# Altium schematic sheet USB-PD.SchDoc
size A2; SheetNumber: 2; SheetTotal: 17
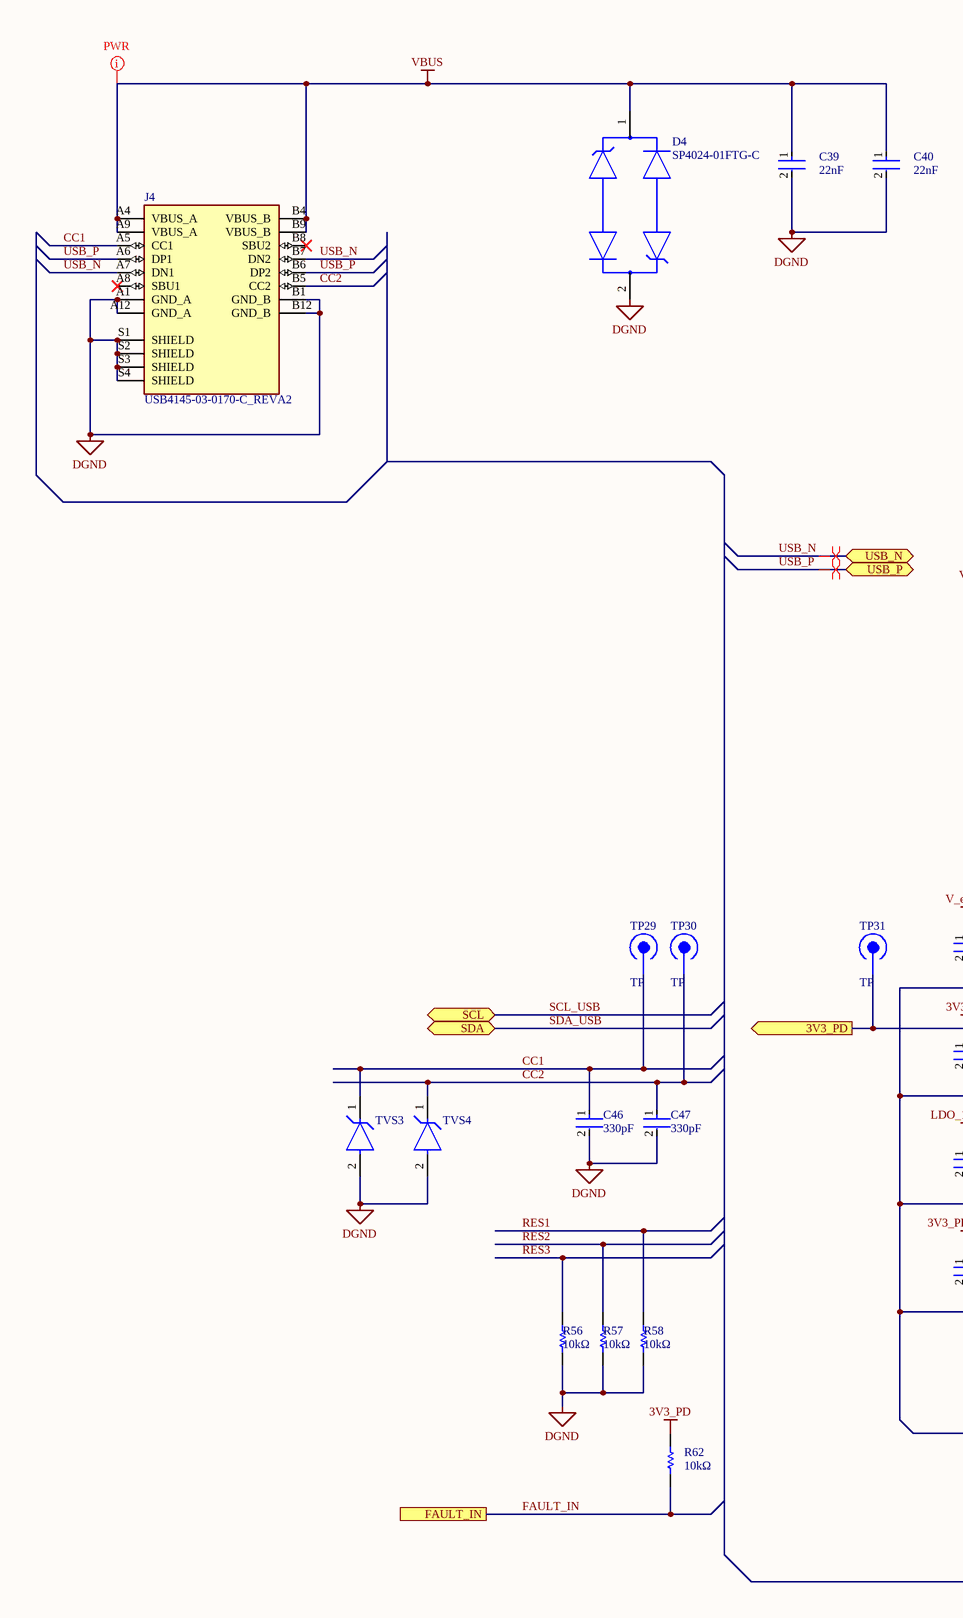
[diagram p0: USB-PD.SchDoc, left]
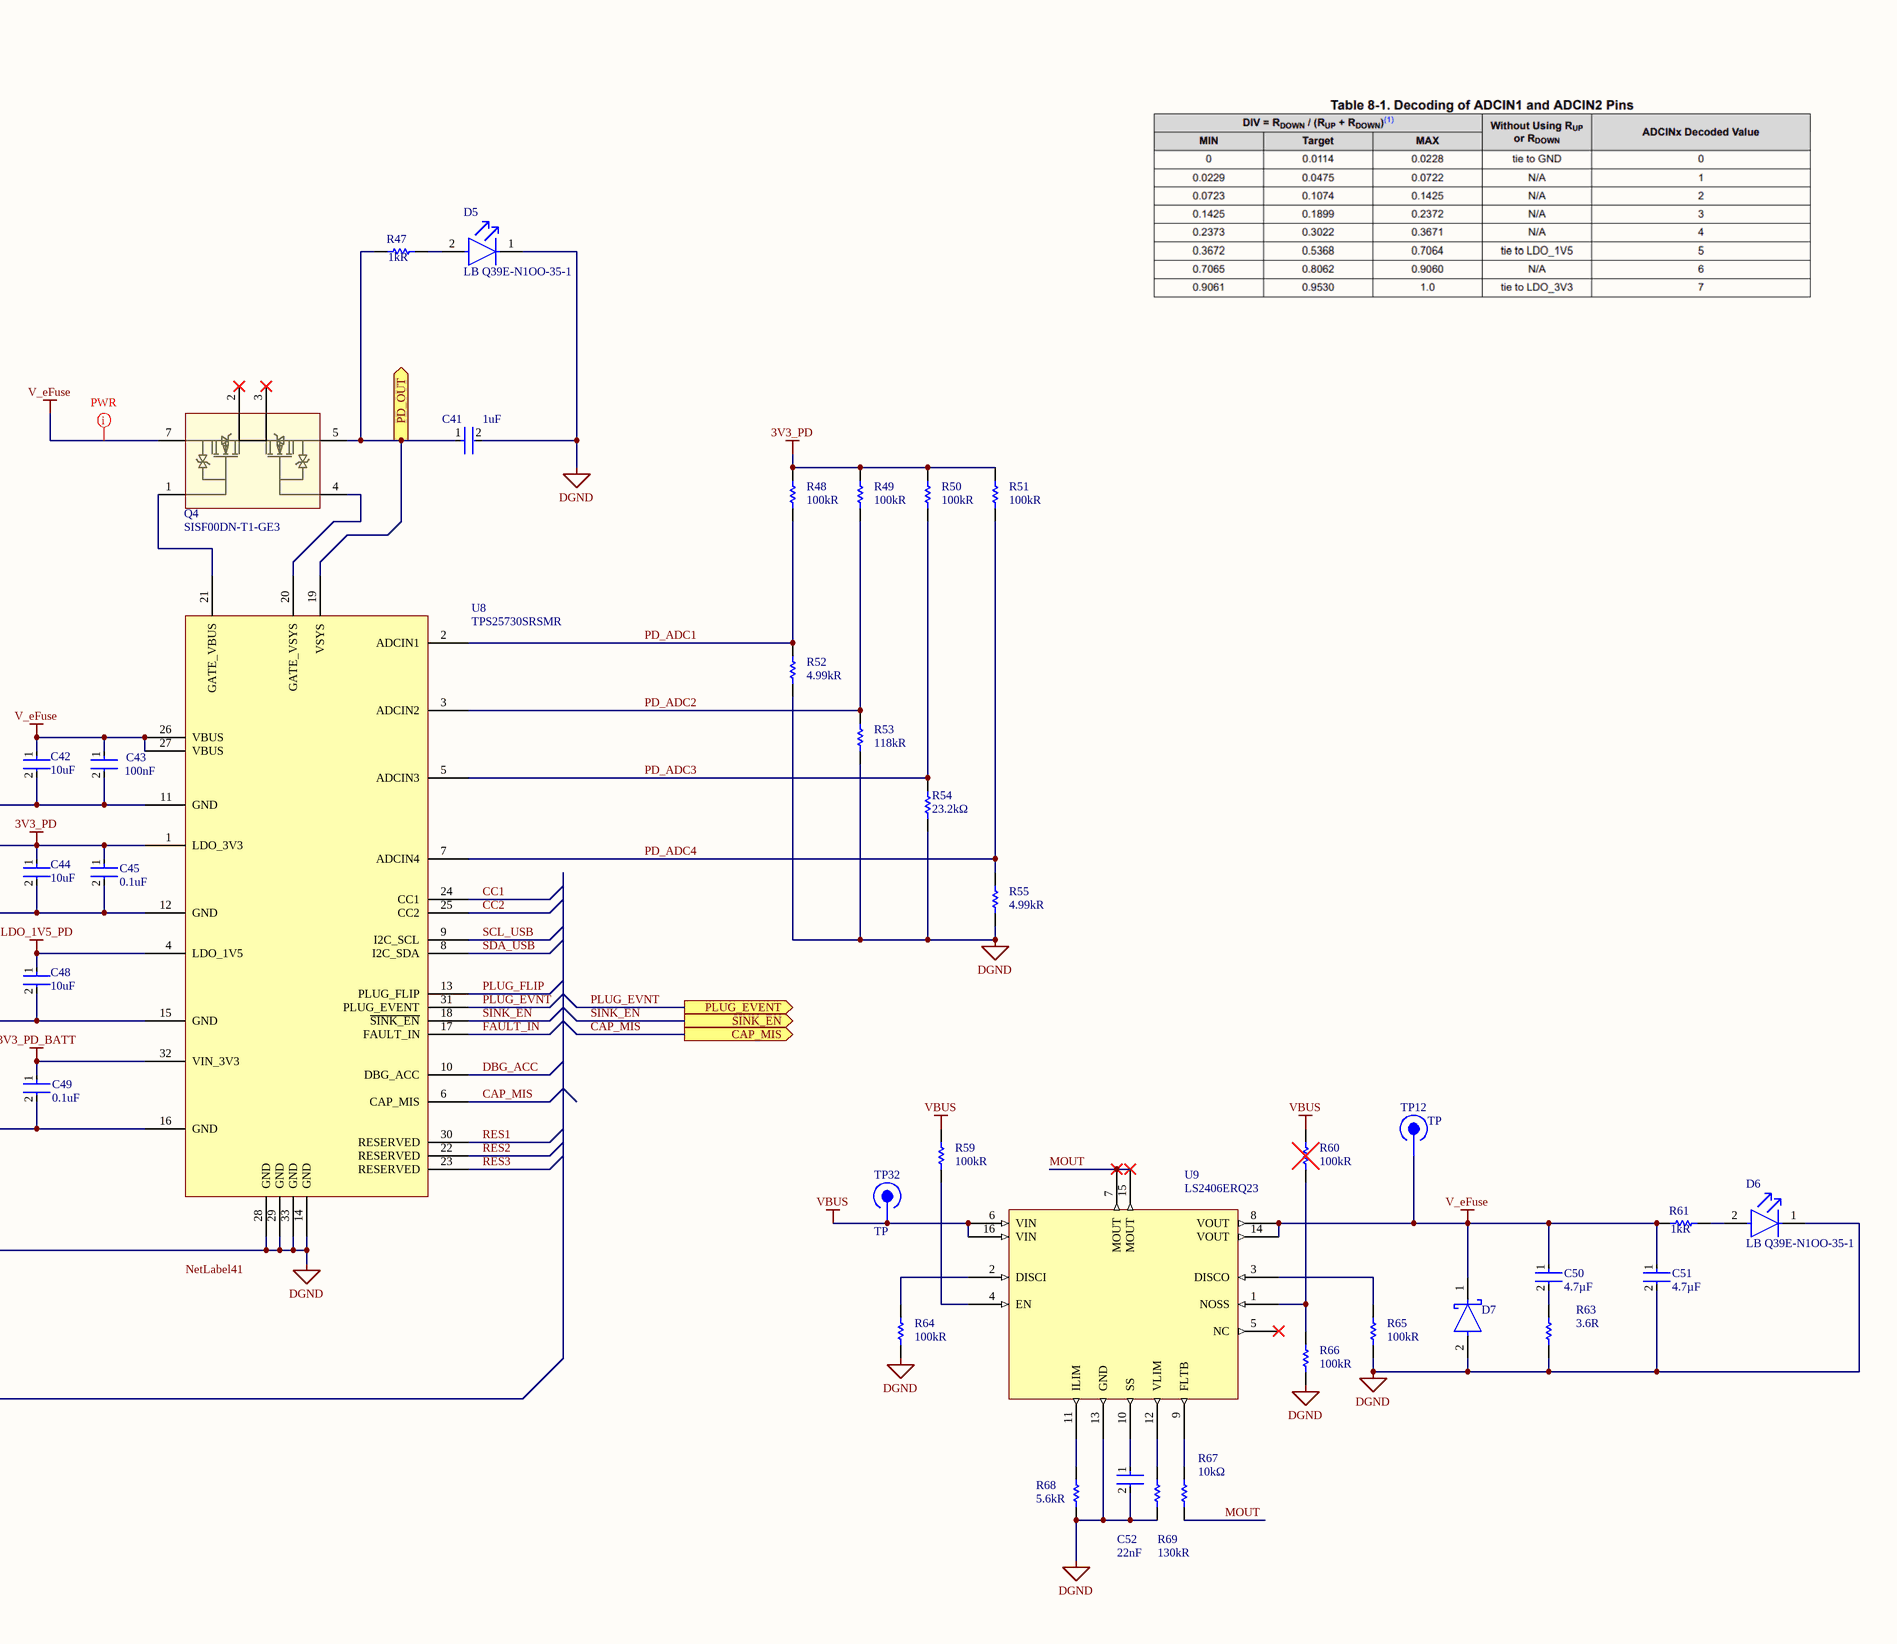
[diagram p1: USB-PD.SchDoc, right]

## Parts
C39  value 22nF  [FP-GRM155-0_05-MFG]  (hidden comment: GRM155R71H223KA12D)
C40  value 22nF  [FP-GRM155-0_05-MFG]  (hidden comment: GRM155R71H223KA12D)
C41  value 1uF  [FP-GCM188-0_1-IPC_B]  (hidden comment: GCM188R71E105KA64J)
C42  value 10uF  [FP-GRM155-0_2-MFG]  (hidden comment: GRM155R61A106ME11D)
C43  value 100nF  [FP-CC0402-IPC_B]  (hidden comment: CC0402KRX7R9BB104)
C44  value 10uF  [FP-GRM155-0_2-MFG]  (hidden comment: GRM155R61A106ME11D)
C45  value 0.1uF  [FP-CC0402-IPC_C]  (hidden comment: CC0402KRX7R7BB104)
C46  value 330pF  [FP-C0402-BB-MFG]  (hidden comment: C0402C331K5RACTU)
C47  value 330pF  [FP-C0402-BB-MFG]  (hidden comment: C0402C331K5RACTU)
C48  value 10uF  [FP-GRM155-0_2-MFG]  (hidden comment: GRM155R61A106ME11D)
C49  value 0.1uF  [FP-CC0402-IPC_C]  (hidden comment: CC0402KRX7R7BB104)
C50  value 4.7µF  [FP-GRM21B-0_15-IPC_A]  (hidden comment: GRM21BR61H475KE51L)
C51  value 4.7µF  [FP-GRM21B-0_15-IPC_A]  (hidden comment: GRM21BR61H475KE51L)
C52  value 22nF  [FP-GRM155-0_05-MFG]  (hidden comment: GRM155R71H223KA12D)
D4  SP4024-01FTG-C  [FP-SP4024-CA-MFG]
D5  LB Q39E-N1OO-35-1  [FP-LB_Q39E-MFG]
D6  LB Q39E-N1OO-35-1  [FP-LB_Q39E-MFG]
D7  PMEG4030ER,115  [FP-SOD123W-MFG]  (value not drawn)
J4  USB4145-03-0170-C_REVA2  [GCT_USB4145-03-0170-C_REVA2]
Q4  SISF00DN-T1-GE3  [New footprint 1]
R47  value 1kR  [FP-ERA2A-MFG]  (hidden comment: ERA-2AEB102X)
R48  value 100kR  [RESC1005X40X25LL10T10]  (hidden comment: RK73H1ETTP1003F)
R49  value 100kR  [RESC1005X40X25LL10T10]  (hidden comment: RK73H1ETTP1003F)
R50  value 100kR  [RESC1005X40X25LL10T10]  (hidden comment: RK73H1ETTP1003F)
R51  value 100kR  [RESC1005X40X25LL10T10]  (hidden comment: RK73H1ETTP1003F)
R52  value 4.99kR  [RESC1005X40X25LL10T10]  (hidden comment: RK73H1ETTP4991F)
R53  value 118kR  [RESC1005X40X25LL10T10]  (hidden comment: RK73H1ETTP1183F)
R54  value 23.2kΩ  [RESC1005X40X25LL10T10]  (hidden comment: RK73H1ETTP2322F)
R55  value 4.99kR  [RESC1005X40X25LL10T10]  (hidden comment: RK73H1ETTP4991F)
R56  value 10kΩ  [RESC1005X40X25LL10T10]  (hidden comment: RK73B1ETTP103J)
R57  value 10kΩ  [RESC1005X40X25LL10T10]  (hidden comment: RK73B1ETTP103J)
R58  value 10kΩ  [RESC1005X40X25LL10T10]  (hidden comment: RK73B1ETTP103J)
R59  value 100kR  [RESC1005X40X25LL10T10]  (hidden comment: RK73H1ETTP1003F)
R60  value 100kR  [RESC1005X40X25LL10T10]  (hidden comment: RK73H1ETTP1003F)  (no BOM)
R61  value 1kR  [FP-ERA2A-MFG]  (hidden comment: ERA-2AEB102X)
R62  value 10kΩ  [RESC1005X40X25LL10T10]  (hidden comment: RK73B1ETTP103J)
R63  value 3.6R  [FP-RK73H2A-MFG]  (hidden comment: RK73H2ATTD3R60F)
R64  value 100kR  [RESC1005X40X25LL10T10]  (hidden comment: RK73H1ETTP1003F)
R65  value 100kR  [RESC1005X40X25LL10T10]  (hidden comment: RK73H1ETTP1003F)
R66  value 100kR  [RESC1005X40X25LL10T10]  (hidden comment: RK73H1ETTP1003F)
R67  value 10kΩ  [RESC1005X40X25LL10T10]  (hidden comment: RK73B1ETTP103J)
R68  value 5.6kR  [RESC1005X40X25LL10T10]  (hidden comment: RK73H1ETTP5601F)
R69  value 130kR  [RESC1005X40X25NL10T10]  (hidden comment: RK73H1ETTP1303F)
TP12  TP  [TP-Footprint-1]
TP29  TP  [TP-Footprint-1]
TP30  TP  [TP-Footprint-1]
TP31  TP  [TP-Footprint-1]
TP32  TP  [TP-Footprint-1]
TVS3  PESD5Z5.0,115  [DIO_BAS716,115]  (value not drawn)
TVS4  PESD5Z5.0,115  [DIO_BAS716,115]  (value not drawn)
U8  TPS25730SRSMR  [QFN40P400X400X100_HS-33N]
U9  LS2406ERQ23  [LS2406ERQ23-Footprint-1]

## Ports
3V3_PD (out), CAP_MIS (out), FAULT_IN, PD_OUT (out), PLUG_EVENT (out), SCL (bidir), SDA (bidir), SINK_EN (out), USB_N (bidir), USB_P (bidir)

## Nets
3V3_PD: C44.1 C45.1 R48.2 R49.2 R50.2 R51.2 R62.2 TP31.1 U8.1(LDO_3V3) ; port 3V3_PD
3V3_PD_BATT: C49.1 U8.32(VIN_3V3)
DGND: C39.2 C40.2 C41.2 C42.2 C43.2 C44.2 C45.2 C46.2 C47.2 C48.2 C49.2 C51.2 C52.2 D4.2 D5.1(C) D6.1(C) D7.2(A) J4.A1(GND_A) J4.A12(GND_A) J4.B1(GND_B) J4.B12(GND_B) J4.S1(SHIELD) J4.S2(SHIELD) J4.S3(SHIELD) J4.S4(SHIELD) R52.1 R53.1 R54.1 R55.1 R56.1 R57.1 R58.1 R63.1 R64.1 R65.1 R66.1 R68.1 R69.1 TVS3.2 TVS4.2 U8.11(GND) U8.12(GND) U8.14(GND) U8.15(GND) U8.16(GND) U8.28(GND) U8.29(GND) U8.33(GND) U9.13(GND)
LDO_1V5_PD: C48.1 U8.4(LDO_1V5)
V_eFuse: C42.1 C43.1 C50.1 C51.1 D7.1(C) Q4.7(S1) R61.2 TP12.1 U8.26(VBUS) U8.27(VBUS) U9.8(VOUT) U9.14(VOUT)
VBUS: C39.1 C40.1 D4.1 J4.A4(VBUS_A) J4.A9(VBUS_A) J4.B4(VBUS_B) J4.B9(VBUS_B) R59.2 R60.2 TP32.1 U9.6(VIN) U9.16(VIN)
CAP_MIS: U8.6(CAP_MIS) ; port CAP_MIS
CC1: C46.1 J4.A5(CC1) TP29.1 TVS3.1 U8.24(CC1)
CC2: C47.1 J4.B5(CC2) TP30.1 TVS4.1 U8.25(CC2)
DBG_ACC: U8.10(DBG_ACC)
FAULT_IN: R62.1 U8.17(FAULT_IN) ; port FAULT_IN
MOUT: R67.1 U9.7(MOUT) U9.15(MOUT)
PD_ADC1: R48.1 R52.2 U8.2(ADCIN1)
PD_ADC2: R49.1 R53.2 U8.3(ADCIN2)
PD_ADC3: R50.1 R54.2 U8.5(ADCIN3)
PD_ADC4: R51.1 R55.2 U8.7(ADCIN4)
PD_OUT: C41.1 Q4.5(S2) R47.2 U8.19(VSYS) ; port PD_OUT
PLUG_EVNT: U8.31(PLUG_EVENT) ; port PLUG_EVENT
PLUG_FLIP: U8.13(PLUG_FLIP)
RES1: R58.2 U8.30(RESERVED)
RES2: R57.2 U8.22(RESERVED)
RES3: R56.2 U8.23(RESERVED)
SCL_USB: U8.9(I2C_SCL) ; port SCL
SDA_USB: U8.8(I2C_SDA) ; port SDA
SINK_EN: U8.18(~{SINK_EN}) ; port SINK_EN
USB_N: J4.A7(DN1) J4.B7(DN2) ; port USB_N
USB_P: J4.A6(DP1) J4.B6(DP2) ; port USB_P
NetC50_2: C50.2 R63.2
NetC52_1: C52.1 U9.10(SS)
NetD5_2: D5.2(A) R47.1
NetD6_2: D6.2(A) R61.1
NetQ4_1: Q4.1(G1) U8.21(GATE_VBUS)
NetQ4_4: Q4.4(G2) U8.20(GATE_VSYS)
NetR59_1: R59.1 U9.4(EN)
NetR60_1: R60.1 R66.2 U9.1(NOSS)
NetR64_2: R64.2 U9.2(DISCI)
NetR65_2: R65.2 U9.3(DISCO)
NetR67_2: R67.2 U9.9(FLTB)
NetR68_2: R68.2 U9.11(ILIM)
NetR69_2: R69.2 U9.12(VLIM)

Not connected (* = marked no-connect by the designer): J4 A8(SBU1)* B8(SBU2)*; Q4 2(S1)* 3(S1)*; U9 5(NC)*

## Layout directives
net class PWR: V_eFuse, VBUS
differential pair; differential pair class USB90_DIFF: USB_N, USB_P

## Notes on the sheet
- Labels drawn without touching a wire or pin: NetLabel41

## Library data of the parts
C39 C40 C52 = CMP-x00115-1: Ceramic Capacitor, Multilayer, Ceramic, 50V, 10% +Tol, 10% -Tol, X7R, 15% TC, 0.022uF, Surface Mount, 0402; Manufacturer: Murata; Vendor: TTI; Template: MR_0402; Reel Width: 8mm
C41 = CMP-x00092-1: Ceramic Capacitor, Multilayer, Ceramic, 25V, 10% +Tol, 10% -Tol, X7R, 15% TC, 1uF, Surface Mount, 0603; Manufacturer: Murata; Vendor: TTI; Template: MR_1608; Reel Width: 8mm
C42 C44 C48 = CMP-x00183-1: Ceramic Capacitor, Multilayer, Ceramic, 10V, 20% +Tol, 20% -Tol, X5R, 15% TC, 10uF, Surface Mount, 0402
C43 = CMP-x00152-1: Ceramic Capacitor, Multilayer, Ceramic, 50V, 10% +Tol, 10% -Tol, X7R, 15% TC, 0.1uF, Surface Mount, 0402
C45 C49 = CMP-001-00094-1: Multilayer Ceramic Capacitor, 0.1 uF, 25 V, ± 10%, X7R, 0402 [1005 Metric]; Rating: 16V; Reel Size: 8mm; Vendor: TTI
C46 C47 = CMP-x00111-1: Ceramic Capacitor, Multilayer, Ceramic, 50V, 10% +Tol, 10% -Tol, X7R, 15% TC, 0.00033uF, Surface Mount, 0402; Manufacturer: Kemet; Vendor: TTI; Template: KM_0402; Reel Width: 8mm
C50 C51 = CMP-001-00268-1: Ceramic Capacitor, Multilayer, Ceramic, 50V, 10% +Tol, 10% -Tol, X5R, 15% TC, 4.7uF, Surface Mount, 0805
D4 = CMP-x00114-1: Trans Voltage Suppressor Diode, 350W, 24V V(RWM), Bidirectional, 1 Element, Silicon; Manufacturer: Littelfuse; Reel Width: 8mm; Vendor: TTI; Template: LF_SOD_323
D5 D6 = CMP-62016-000029-1: LED BLUE DIFFUSED 0603 SMD; Lens Color: White; Viewing Angle: 130°; Dominant Wavelength: 470nm; Lens Style: Flat; Luminous Intensity: 42mcd; Forward Voltage: 2.85V; Test Current: 5mA; Number of LEDs: 1; Lens Size: 0.8mm; Luminous Flux: 0.13lm
D7 = CMP-x00083-1: Rectifier Diode, Schottky, 1 Phase, 1 Element, 3A, 40V V(RRM), Silicon; Manufacturer: Nexperia; Vendor: TTI; Template: NX_SOD_123W_2; Reel Width: 8mm
J4 = CMP-349-000000-01-A-2
Q4 = CMP-x00106-2: Power Field-Effect Transistor; Manufacturer: Vishay; Vendor: TTI; Template: VS_PP12_8; Value: 30V; Reel Width: 12mm
R47 R61 = CMP-x00015-3: Fixed Resistor, Thin Film, 0.063W, 1000ohm, 50V, 0.1% +/-Tol, 25ppm/Cel, Surface Mount, 0402; Manufacturer: Panasonic; Rating: 63mW; Vendor: TTI; Reel Width: 8mm; Template: PS_0402
R48-R51 R59 R60 R64-R66 = CMP-x00162-1: Fixed Resistor, Metal Glaze/thick Film, 0.1W, 100000ohm, 75V, 1% +/-Tol, 100ppm/Cel, Surface Mount, 0402
R52 R55 = CMP-x00172-1: Fixed Resistor, Metal Glaze/thick Film, 0.1W, 4990ohm, 75V, 1% +/-Tol, 100ppm/Cel, Surface Mount, 0402
R53 = CMP-x00173-1: Fixed Resistor, Metal Glaze/thick Film, 0.1W, 118000ohm, 75V, 1% +/-Tol, 100ppm/Cel, Surface Mount, 0402
R54 = CMP-009-00229-1: Fixed Resistor, Metal Glaze/thick Film, 0.1W, 23200ohm, 75V, 1% +/-Tol, 100ppm/Cel, Surface Mount, 0402; Vendor: TTI; Rating: 1/10W
R56-R58 R62 R67 = CMP-009-00227-1: Fixed Resistor, Metal Glaze/thick Film, 0.1W, 10000ohm, 75V, 5% +/-Tol, 200ppm/Cel, Surface Mount, 0402; Rating: 1/10W; Vendor: TTI
R63 = CMP-x00167-1: Fixed Resistor, Metal Glaze/thick Film, 0.25W, 3.6ohm, 150V, 1% +/-Tol, 200ppm/Cel, Surface Mount, 0805
R68 = CMP-x00164-1: Fixed Resistor, Metal Glaze/thick Film, 0.1W, 5600ohm, 75V, 1% +/-Tol, 100ppm/Cel, Surface Mount, 0402
R69 = CMP-2002-03957-1: Manufacturer: KOA Speer
TP12 TP29-TP32 = CMP-001-0086-3: digital shovel test point
TVS3 TVS4 = CMP-x00209-4: Trans Voltage Suppressor Diode, 180W, 5V V(RWM), Unidirectional, 1 Element, Silicon; Manufacturer: Nexperia; Template: NX_SOD_523_2
U8 = CMP-x00105-1: Sink-only USB Type-C® and USB Power Delivery (PD) controller with no firmware development required 32-VQFN -40 to 125; Manufacturer: Texas Instruments; Template: TI_VQFN_32; Reel Width: 12mm
U9 = CMP-x00113-1: 28V/6A Efuse With True Rcb & Frs; Manufacturer: Littelfuse; Reel Width: 12mm; Template: LF_QFN_16; Vendor: TTI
